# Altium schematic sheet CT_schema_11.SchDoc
size 147 x 119 mm
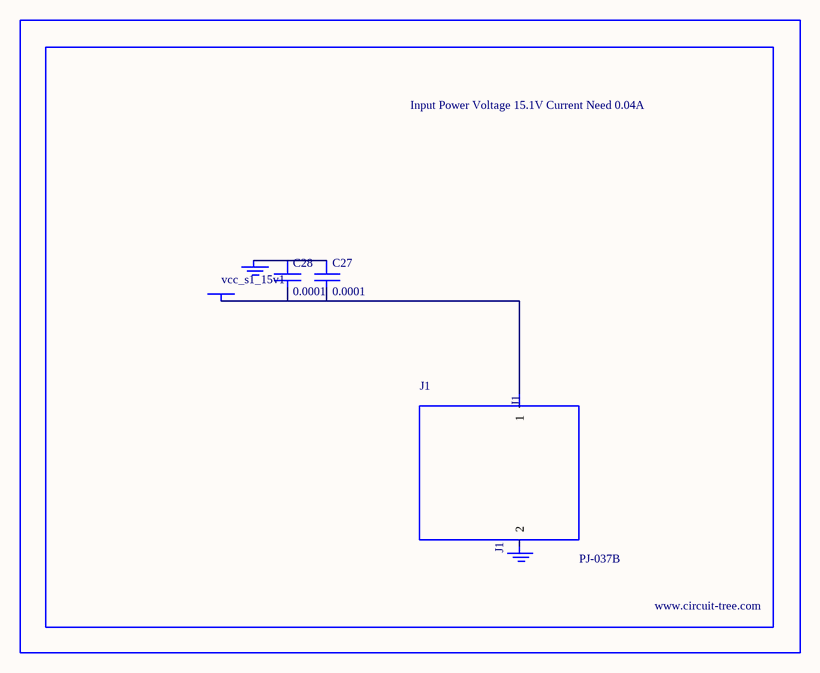
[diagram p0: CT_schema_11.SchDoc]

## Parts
BORDER10  (no value)
C27  0.0001  [EXV-9H]
C28  0.0001  [EXV-9H]
GND_INSTANCE_10_0  (no value)
GND_INSTANCE_10_1  (no value)
J1  PJ-037B  [PJ-037B_PACKAGE]
POWER_INSTANCE_10_0  vcc_s1_15v1

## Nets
NetC27_1: C27.1 C28.1 GND_INSTANCE_10_0.0(GND)
NetC27_2: C27.2 C28.2 J1.1 POWER_INSTANCE_10_0.0(PWR)

Not connected (* = marked no-connect by the designer): GND_INSTANCE_10_1 0(GND); J1 2

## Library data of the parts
BORDER10 = BORDER_PAGE10
C27 C28 = EDK107M035A9HAA
GND_INSTANCE_10_0 GND_INSTANCE_10_1 = GND
POWER_INSTANCE_10_0 = PWR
